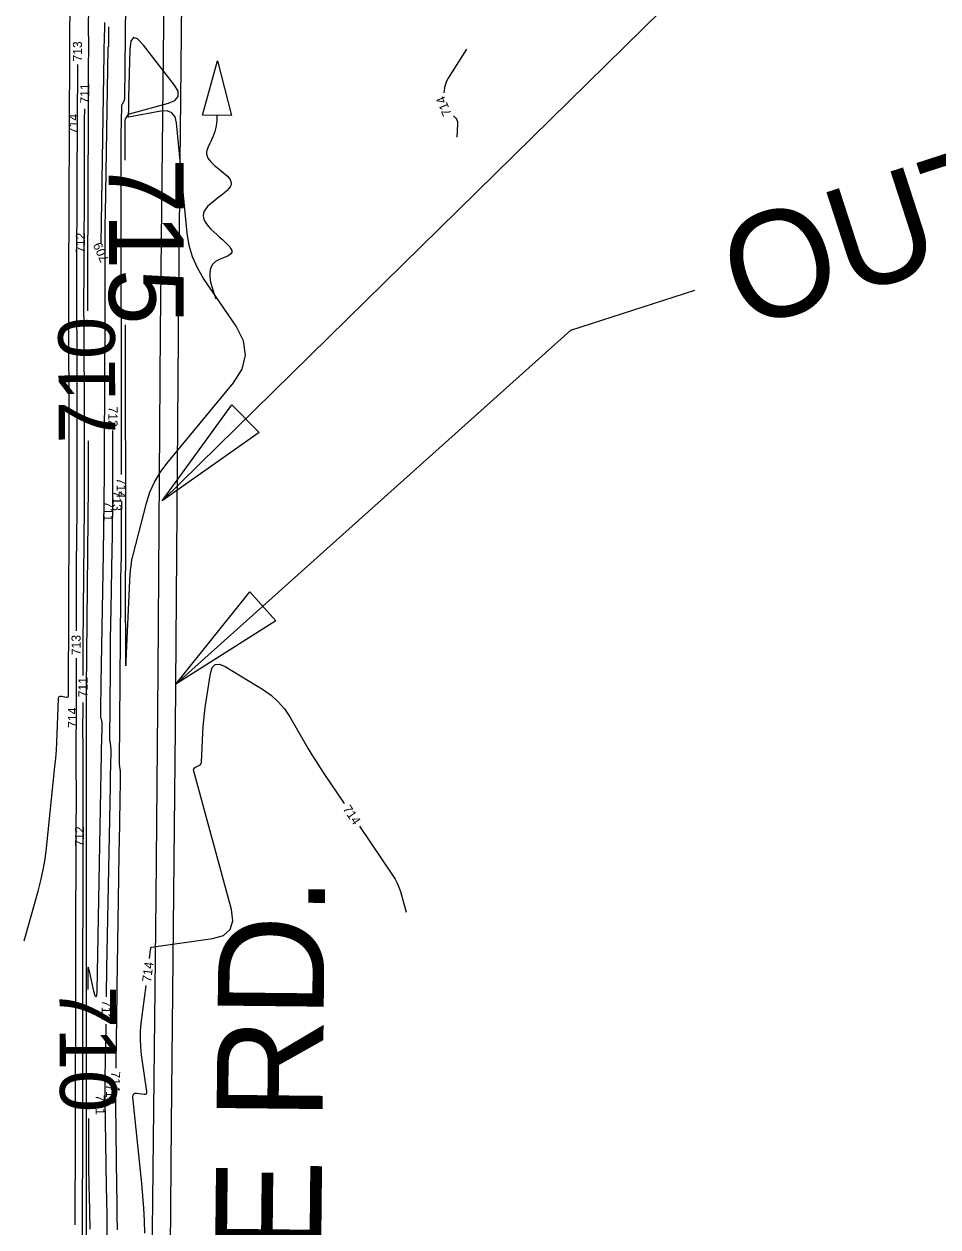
# Model space of a CAD drawing. Extents: x -468548933 to 3387700, y -306089263 to 1207014.
# Drawn here: x 1835208 to 1835612, y 537245 to 537776 of the extents above; entities that cross this region are included whole.
import ezdxf

# ---------------------------------------------------------------- set-up
doc = ezdxf.new("R2010")
doc.units = 0
for name, color, linetype in [('DT_X_Contour_Minor', 7, 'Continuous'), ('Level 19', 7, 'Continuous'), ('Level 40', 7, 'Continuous'), ('Level 56', 7, 'Continuous')]:
    doc.layers.add(name, color=color, linetype=linetype)

msp = doc.modelspace()

# ---------------------------------------------------------------- linework, layer by layer
at = {"layer": 'DT_X_Contour_Minor'}
for points in [[(1835208.43, 537371.04), (1835214.63, 537392.88), (1835215.86, 537397.58), (1835216.88, 537402.32), (1835217.69, 537407.1), (1835218.3, 537411.92), (1835222.08, 537447.93), (1835222.43, 537451.53), (1835222.71, 537455.13), (1835222.93, 537458.74), (1835223.09, 537462.36), (1835223.63, 537477.88), (1835223.73, 537478.46), (1835223.99, 537478.83), (1835224.41, 537479), (1835224.99, 537478.98), (1835227.14, 537478.57), (1835227.55, 537478.56), (1835227.84, 537478.68), (1835228.01, 537478.94), (1835228.07, 537479.34), (1835228.35, 537556.11), (1835228.35, 537556.14), (1835228.35, 537556.17), (1835228.35, 537556.2), (1835228.35, 537556.23), (1835228.35, 537556.33), (1835228.35, 537556.35), (1835228.35, 537556.37), (1835228.35, 537556.39), (1835228.35, 537556.42), (1835228.33, 537573.32), (1835228.33, 537576.94), (1835228.32, 537580.57), (1835228.32, 537584.19), (1835228.32, 537587.81), (1835228.25, 537656.96), (1835228.25, 537657.19), (1835228.25, 537657.43), (1835228.25, 537657.67), (1835228.25, 537657.9), (1835228.24, 537658.68), (1835228.24, 537658.84), (1835228.24, 537659.01), (1835228.24, 537659.18), (1835228.24, 537659.34), (1835228.25, 537660.88), (1835228.25, 537661.21), (1835228.25, 537661.54), (1835228.25, 537661.87), (1835228.25, 537662.2), (1835228.69, 537763.25), (1835228.69, 537763.33), (1835228.68, 537763.41), (1835228.68, 537763.49), (1835228.66, 537763.57), (1835228.61, 537763.84), (1835228.6, 537763.89), (1835228.6, 537763.95), (1835228.59, 537764), (1835228.59, 537764.06), (1835229.14, 537840.75)], [(1835253.59, 537826.49), (1835252.72, 537742.53), (1835252.69, 537742.17), (1835252.62, 537741.83), (1835252.49, 537741.51), (1835252.32, 537741.2), (1835251.69, 537740.2), (1835251.57, 537739.98), (1835251.49, 537739.75), (1835251.43, 537739.52), (1835251.41, 537739.27), (1835251.2, 537726.2), (1835251.17, 537723.4), (1835251.14, 537720.6), (1835251.12, 537717.79), (1835251.12, 537714.99), (1835251.35, 537576.81)], [(1835236.55, 537648.98), (1835236.55, 537655.87), (1835236.57, 537664.54), (1835236.83, 537735.51), (1835236.85, 537739.51), (1835236.86, 537743.51), (1835236.88, 537747.51), (1835236.89, 537751.51), (1835236.97, 537770.14), (1835236.97, 537770.17), (1835236.97, 537770.19), (1835236.97, 537770.21), (1835236.97, 537770.23), (1835236.95, 537770.3), (1835236.95, 537770.31), (1835236.95, 537770.33), (1835236.95, 537770.34), (1835236.95, 537770.36), (1835237.07, 537786.75)], [(1835245.75, 537774.39), (1835245.66, 537765.88), (1835245.66, 537765.8), (1835245.64, 537765.72), (1835245.61, 537765.64), (1835245.57, 537765.56), (1835245.42, 537765.32), (1835245.39, 537765.27), (1835245.37, 537765.21), (1835245.35, 537765.16), (1835245.35, 537765.1), (1835244.17, 537691.78), (1835244.11, 537687.07), (1835244.06, 537682.36), (1835244.04, 537677.65), (1835244.04, 537672.95), (1835244.06, 537657.57), (1835244.07, 537654.27), (1835244.07, 537650.97), (1835244.06, 537647.68), (1835244.05, 537644.38), (1835243.86, 537589.16), (1835243.79, 537577.33), (1835243.69, 537565.5), (1835243.54, 537553.67), (1835243.35, 537541.84), (1835242.32, 537484.75), (1835242.29, 537483.02), (1835242.27, 537481.29), (1835242.25, 537479.56), (1835242.23, 537477.83), (1835242.17, 537470.34), (1835242.18, 537470.05), (1835242.21, 537469.76), (1835242.25, 537469.47), (1835242.32, 537469.19), (1835242.62, 537468.07), (1835242.64, 537467.97), (1835242.66, 537467.87), (1835242.68, 537467.77), (1835242.7, 537467.66), (1835242.74, 537467.33), (1835242.75, 537467.26), (1835242.76, 537467.18), (1835242.76, 537467.11), (1835242.76, 537467.04), (1835242.72, 537464.1), (1835242.71, 537463.47), (1835242.7, 537462.84), (1835242.68, 537462.21), (1835242.67, 537461.58), (1835240.52, 537348.87), (1835240.4, 537346.79), (1835240.15, 537346.07), (1835239.76, 537346.72), (1835239.24, 537348.74), (1835237.31, 537357.56), (1835236.95, 537358.97), (1835236.7, 537359.43), (1835236.55, 537358.93), (1835236.51, 537357.47), (1835236.55, 537349.55)], [(1835243.95, 537776.29), (1835243.9, 537771.72), (1835243.9, 537771.71), (1835243.9, 537771.69), (1835243.89, 537771.67), (1835243.88, 537771.65), (1835243.85, 537771.6), (1835243.84, 537771.59), (1835243.84, 537771.58), (1835243.83, 537771.57), (1835243.83, 537771.55), (1835242.34, 537678.75)], [(1835253.17, 537538.02), (1835253.11, 537530.73), (1835253.1, 537529.11), (1835253.1, 537527.49), (1835253.09, 537525.88), (1835253.09, 537524.26), (1835253.16, 537498.02), (1835253.21, 537493.8), (1835253.31, 537492.4), (1835253.48, 537493.8), (1835253.71, 537498.01), (1835255.33, 537533.05), (1835255.38, 537533.88), (1835255.45, 537534.71), (1835255.54, 537535.54), (1835255.65, 537536.37), (1835256.07, 537539.07), (1835256.16, 537539.65), (1835256.27, 537540.22), (1835256.4, 537540.79), (1835256.53, 537541.36), (1835262.44, 537564.17), (1835263.95, 537568.93), (1835265.95, 537573.44), (1835268.44, 537577.7), (1835271.42, 537581.71), (1835300.9, 537617.25), (1835304.72, 537623.32), (1835306.18, 537629.5), (1835305.31, 537635.79), (1835302.08, 537642.2), (1835287.71, 537663.3), (1835284.95, 537667.93), (1835282.83, 537672.8), (1835281.34, 537677.9), (1835280.5, 537683.23), (1835275.76, 537731.97), (1835275.1, 537734.67), (1835273.73, 537736.44), (1835271.65, 537737.26), (1835268.87, 537737.14), (1835254.59, 537734.47), (1835254.45, 537734.46), (1835254.36, 537734.51), (1835254.32, 537734.6), (1835254.34, 537734.74), (1835254.51, 537735.36), (1835254.53, 537735.43), (1835254.56, 537735.5), (1835254.59, 537735.57), (1835254.63, 537735.64), (1835254.75, 537735.87), (1835254.79, 537735.91), (1835254.82, 537735.95), (1835254.87, 537735.97), (1835254.92, 537735.99), (1835272.12, 537740.64), (1835275.05, 537741.89), (1835276.48, 537743.65), (1835276.4, 537745.91), (1835274.82, 537748.67), (1835261.15, 537766.33), (1835258.57, 537769.04), (1835256.7, 537769.61), (1835255.53, 537768.04), (1835255.06, 537764.33), (1835254.57, 537743.34), (1835254.55, 537742.48), (1835254.54, 537741.61), (1835254.52, 537740.74), (1835254.51, 537739.87), (1835254.48, 537736.69), (1835254.45, 537736.27), (1835254.36, 537735.86), (1835254.21, 537735.47), (1835254.01, 537735.1), (1835253.26, 537733.92), (1835253.12, 537733.66), (1835253.02, 537733.39), (1835252.95, 537733.11), (1835252.93, 537732.81), (1835252.9, 537730.95), (1835252.89, 537730.55), (1835252.89, 537730.15), (1835252.89, 537729.76), (1835252.89, 537729.36), (1835252.91, 537715.56)], [(1835403.76, 537764.52), (1835395.67, 537751.74), (1835394.94, 537750.43), (1835394.39, 537749.06), (1835394.01, 537747.64), (1835393.8, 537746.16), (1835393.73, 537745.23)], [(1835231.97, 537757.72), (1835231.75, 537706.34), (1835231.72, 537700.33), (1835231.7, 537694.33), (1835231.67, 537688.32), (1835231.65, 537682.31), (1835231.58, 537661.8), (1835231.57, 537658.04), (1835231.57, 537654.29), (1835231.57, 537650.53), (1835231.59, 537646.77), (1835231.66, 537634.51), (1835231.67, 537631.88), (1835231.68, 537629.25), (1835231.69, 537626.62), (1835231.7, 537623.99), (1835231.74, 537574.7), (1835231.74, 537569.08), (1835231.72, 537563.45), (1835231.69, 537557.82), (1835231.65, 537552.2), (1835231.48, 537533.82), (1835231.45, 537529.88), (1835231.43, 537525.94), (1835231.41, 537522), (1835231.4, 537518.06), (1835231.39, 537507.73)], [(1835234.46, 537488.13), (1835234.46, 537489.58), (1835234.47, 537492.6), (1835234.48, 537495.63), (1835234.5, 537498.66), (1835234.52, 537501.68), (1835235.08, 537562.59), (1835235.11, 537567.03), (1835235.14, 537571.47), (1835235.15, 537575.91), (1835235.15, 537580.35), (1835235.14, 537594.85), (1835235.13, 537597.96), (1835235.12, 537601.06), (1835235.11, 537604.17), (1835235.1, 537607.28), (1835234.93, 537636.88), (1835234.9, 537643.22), (1835234.88, 537649.56), (1835234.88, 537655.9), (1835234.9, 537662.25), (1835235.09, 537714.6), (1835235.12, 537720.86), (1835235.14, 537727.12), (1835235.17, 537733.37), (1835235.19, 537738.12)], [(1835397.92, 537735.09), (1835398.34, 537734.73), (1835398.99, 537734.04), (1835399.44, 537733.27), (1835399.69, 537732.41), (1835399.74, 537731.47), (1835399.45, 537725.71)], [(1835253.03, 537642.9), (1835253.2, 537540.77), (1835253.2, 537540.61), (1835253.2, 537540.44), (1835253.2, 537540.28), (1835253.2, 537540.11), (1835253.2, 537539.58), (1835253.2, 537539.46), (1835253.19, 537539.35), (1835253.19, 537539.23), (1835253.19, 537539.12), (1835253.18, 537538.53), (1835253.18, 537538.4), (1835253.18, 537538.27), (1835253.17, 537538.14), (1835253.17, 537538.02)], [(1835236.07, 537220.78), (1835235.98, 537252.2), (1835235.98, 537252.49), (1835235.98, 537252.78), (1835235.98, 537253.07), (1835235.98, 537253.35), (1835235.98, 537254.29), (1835235.98, 537254.49), (1835235.98, 537254.69), (1835235.98, 537254.89), (1835235.98, 537255.09), (1835235.98, 537256.04), (1835235.98, 537256.24), (1835235.98, 537256.44), (1835235.98, 537256.64), (1835235.98, 537256.85), (1835236.05, 537366.66), (1835236.05, 537366.77), (1835236.05, 537366.87), (1835236.05, 537366.98), (1835236.05, 537367.08), (1835236.05, 537367.43), (1835236.05, 537367.5), (1835236.05, 537367.58), (1835236.05, 537367.65), (1835236.05, 537367.72), (1835235.99, 537468.53), (1835235.99, 537469.91), (1835235.99, 537471.29), (1835235.99, 537472.66), (1835235.99, 537474.04), (1835235.99, 537478.55), (1835236, 537479.51), (1835236, 537480.48), (1835236.01, 537481.44), (1835236.01, 537482.41), (1835236.83, 537572.04), (1835236.85, 537573.76), (1835236.85, 537575.48), (1835236.86, 537577.21), (1835236.86, 537578.93), (1835236.85, 537584.56), (1835236.85, 537585.77), (1835236.85, 537586.97), (1835236.84, 537588.18), (1835236.84, 537589.39), (1835236.82, 537591.72)], [(1835244.8, 537346.22), (1835244.81, 537347.16), (1835244.87, 537351.03), (1835244.94, 537354.9), (1835245.01, 537358.76), (1835246.55, 537439.29), (1835246.58, 537441.26), (1835246.62, 537443.24), (1835246.65, 537445.21), (1835246.68, 537447.19), (1835246.81, 537455.78), (1835246.8, 537456.09), (1835246.79, 537456.4), (1835246.77, 537456.72), (1835246.73, 537457.03), (1835246.58, 537458.15), (1835246.56, 537458.31), (1835246.53, 537458.48), (1835246.5, 537458.64), (1835246.46, 537458.79), (1835246.32, 537459.31), (1835246.29, 537459.42), (1835246.27, 537459.54), (1835246.26, 537459.65), (1835246.26, 537459.76), (1835246.52, 537490.79), (1835246.58, 537497.44), (1835246.66, 537504.08), (1835246.75, 537510.73), (1835246.87, 537517.38), (1835247.34, 537543.74), (1835247.43, 537549.39), (1835247.5, 537555.04), (1835247.55, 537560.69), (1835247.58, 537566.34), (1835247.68, 537594.63), (1835247.69, 537596.14)], [(1835251.37, 537564.81), (1835251.37, 537562.55), (1835251.36, 537559.85), (1835251.35, 537557.16), (1835251.32, 537548.35), (1835251.31, 537546.47), (1835251.3, 537544.58), (1835251.27, 537542.69), (1835251.24, 537540.81), (1835251.07, 537531.06), (1835251.03, 537528.97), (1835251, 537526.88), (1835250.98, 537524.79), (1835250.96, 537522.7), (1835250.35, 537449.38), (1835250.35, 537449.35), (1835250.36, 537449.31), (1835250.36, 537449.28), (1835250.37, 537449.24), (1835250.4, 537449.13), (1835250.4, 537449.11), (1835250.41, 537449.09), (1835250.41, 537449.06), (1835250.42, 537449.04), (1835250.73, 537446.65), (1835250.79, 537446.14), (1835250.83, 537445.62), (1835250.85, 537445.11), (1835250.85, 537444.59), (1835250.64, 537429.77), (1835250.59, 537426.71), (1835250.54, 537423.64), (1835250.49, 537420.58), (1835250.43, 537417.51), (1835250.24, 537407.5), (1835250.2, 537405.35), (1835250.16, 537403.2), (1835250.13, 537401.06), (1835250.1, 537398.91), (1835249.41, 537350.54), (1835249.34, 537345.31), (1835249.26, 537340.08), (1835249.19, 537334.85), (1835249.11, 537329.62), (1835248.9, 537314.87)], [(1835231.38, 537495.73), (1835231.36, 537466.67), (1835231.35, 537462.26), (1835231.35, 537457.86), (1835231.35, 537453.46), (1835231.35, 537449.06), (1835231.36, 537434.67), (1835231.36, 537431.59), (1835231.36, 537428.51), (1835231.35, 537425.43), (1835231.34, 537422.34), (1835231.13, 537364.42), (1835231.11, 537359.75), (1835231.1, 537355.09), (1835231.09, 537350.42), (1835231.09, 537345.76), (1835231.08, 537330.52), (1835231.08, 537327.25), (1835231.07, 537323.98), (1835231.06, 537320.72), (1835231.06, 537317.45), (1835230.92, 537270.17), (1835230.9, 537260.03), (1835230.89, 537249.9), (1835230.89, 537245.73)], [(1835263.81, 537363.23), (1835264.29, 537367.07), (1835264.31, 537367.21), (1835264.33, 537367.34), (1835264.34, 537367.47), (1835264.36, 537367.6), (1835264.41, 537368.04), (1835264.44, 537368.12), (1835264.48, 537368.18), (1835264.54, 537368.23), (1835264.62, 537368.25), (1835291.55, 537371.99), (1835296.41, 537373.39), (1835299.44, 537376), (1835300.65, 537379.81), (1835300.03, 537384.83), (1835283.35, 537445.93), (1835283.28, 537446.48), (1835283.38, 537446.95), (1835283.66, 537447.34), (1835284.13, 537447.65), (1835285.93, 537448.52), (1835286.26, 537448.74), (1835286.51, 537449.02), (1835286.67, 537449.36), (1835286.74, 537449.76), (1835287.34, 537462.85), (1835287.51, 537465.65), (1835287.74, 537468.44), (1835288.06, 537471.23), (1835288.44, 537474.01), (1835290.73, 537489.03), (1835291.5, 537491.64), (1835292.85, 537493.01), (1835294.77, 537493.15), (1835297.26, 537492.07), (1835314.16, 537481.7), (1835317.6, 537479.29), (1835320.67, 537476.53), (1835323.36, 537473.4), (1835325.68, 537469.91), (1835333.75, 537456.04), (1835335.51, 537453.09), (1835337.31, 537450.16), (1835339.16, 537447.27), (1835341.07, 537444.4), (1835349.75, 537431.57)], [(1835234.33, 537233.31), (1835234.29, 537247.16), (1835234.28, 537250.13), (1835234.28, 537253.09), (1835234.28, 537256.06), (1835234.29, 537259.03), (1835234.33, 537272.98), (1835234.34, 537275.97), (1835234.34, 537278.96), (1835234.35, 537281.95), (1835234.35, 537284.93), (1835234.39, 537355.46), (1835234.39, 537359.2), (1835234.4, 537362.95), (1835234.41, 537366.69), (1835234.42, 537370.43), (1835234.47, 537382.65), (1835234.48, 537385.27), (1835234.48, 537387.89), (1835234.48, 537390.51), (1835234.48, 537393.13), (1835234.45, 537458.17), (1835234.44, 537462.49), (1835234.44, 537466.81), (1835234.45, 537471.13), (1835234.45, 537475.46), (1835234.45, 537476.13)], [(1835356.48, 537421.63), (1835371.12, 537399.98), (1835372.19, 537398.27), (1835373.11, 537396.48), (1835373.89, 537394.63), (1835374.53, 537392.71), (1835377.16, 537383.59)], [(1835261.78, 537241.97), (1835261.6, 537247.47), (1835261.32, 537252.97), (1835260.92, 537258.46), (1835260.42, 537263.94), (1835256.51, 537302.05), (1835256.55, 537302.9), (1835256.85, 537303.47), (1835257.43, 537303.76), (1835258.28, 537303.77), (1835261.5, 537303.34), (1835262.1, 537303.35), (1835262.49, 537303.55), (1835262.69, 537303.95), (1835262.68, 537304.54), (1835260.31, 537320.69), (1835259.92, 537324.15), (1835259.77, 537327.61), (1835259.85, 537331.08), (1835260.17, 537334.55), (1835262.3, 537351.33)], [(1835245.53, 537208.54), (1835245.2, 537237.69), (1835245.13, 537243.93), (1835245.05, 537250.18), (1835244.96, 537256.42), (1835244.87, 537262.67), (1835244.29, 537300.93), (1835244.27, 537303.35), (1835244.26, 537305.76), (1835244.26, 537308.18), (1835244.29, 537310.6), (1835244.4, 537318.49), (1835244.43, 537320.18), (1835244.45, 537321.87), (1835244.47, 537323.56), (1835244.5, 537325.26), (1835244.63, 537334.22)], [(1835248.8, 537302.87), (1835248.83, 537300.95), (1835248.84, 537300.38), (1835248.85, 537299.81), (1835248.85, 537299.25), (1835248.86, 537298.68), (1835249.28, 537262.45), (1835249.35, 537256.13), (1835249.44, 537249.82), (1835249.54, 537243.5)], [(1835236.83, 537292.61), (1835236.93, 537271.84), (1835236.95, 537268.57), (1835236.99, 537265.31), (1835237.04, 537262.04), (1835237.1, 537258.77), (1835237.41, 537243.69)]]:
    msp.add_lwpolyline(points, dxfattribs=at)
at = {"layer": 'Level 40'}
for p, q in [((1835449.84, 537640.44), (1835504.55, 537658.2)), ((1835449.84, 537640.44), (1835275.42, 537484.22)), ((1835269.4, 537565.22), (1835300.08, 537607.55)), ((1835300.08, 537607.55), (1835312.14, 537595.33)), ((1835312.14, 537595.33), (1835269.4, 537565.22)), ((1835275.42, 537484.22), (1835308.12, 537525.01)), ((1835308.12, 537525.01), (1835319.58, 537512.22)), ((1835319.58, 537512.22), (1835275.42, 537484.22))]:
    msp.add_line(p, q, dxfattribs=at)
msp.add_lwpolyline([(1835269.4, 537565.22), (1835546.87, 537837.73), (1835603.69, 537856.17)], dxfattribs=at)
at = {"layer": 'Level 56'}
for p, q in [((1835287.16, 537735.35), (1835293.78, 537759.3)), ((1835293.78, 537759.3), (1835300.03, 537735.25)), ((1835300.03, 537735.25), (1835287.16, 537735.35))]:
    msp.add_line(p, q, dxfattribs=at)
for points in [[(1835272.54, 537989.9), (1835270.63, 537829.71), (1835268.58, 537639.91), (1835267.46, 537489.92), (1835266.63, 537389.92), (1835264.41, 537189.93), (1835263.9, 537104.93), (1835263.77, 536939.93), (1835262.99, 536824.67)], [(1835271.56, 536827.69), (1835271.95, 537089.9), (1835273.57, 537289.9), (1835275.29, 537464.69), (1835276.71, 537656.89), (1835279.46, 537914.68), (1835280.54, 537989.88)]]:
    msp.add_lwpolyline(points, dxfattribs=at)
msp.add_spline([(1835293.53, 537735.33), (1835293.53, 537734.38), (1835291.21, 537724.52), (1835288.99, 537718.28), (1835299.92, 537705.48), (1835287.44, 537691.02), (1835299.7, 537674.13), (1835292.97, 537670.78), (1835293.03, 537654.3)], degree=3, dxfattribs=at)

# ---------------------------------------------------------------- texts
at = {"layer": 'Level 19'}
for s, height, rotation, p in [('713', 4, 90.0521, (1835234, 537759.05)), ('711', 4, 89.7523, (1835237.2, 537740.46)), ('714', 4, 112.4452, (1835397.24, 537735.91)), ('714', 4, 89.7516, (1835232.19, 537726.98)), ('715', 33, 270.0941, (1835245.81, 537716.53)), ('712', 4, 89.7905, (1835235.28, 537674.57)), ('709', 4, 113.8187, (1835245.99, 537671.53)), ('710', 25, 90.308, (1835248.79, 537590.65)), ('712', 4, 269.8901, (1835245.71, 537606.79)), ('714', 4, 270.0819, (1835249.35, 537575.28)), ('711', 4, 269.4037, (1835243.65, 537565.03)), ('713', 4, 269.799, (1835247.5, 537569.66)), ('713', 4, 89.9476, (1835233.38, 537497.05)), ('711', 4, 89.9476, (1835236.45, 537478.47)), ('714', 4, 89.9476, (1835231.81, 537464.99)), ('714', 4, 304.0829, (1835348.95, 537429.18)), ('712', 4, 89.9897, (1835234.92, 537412.58)), ('714', 4, 82.7838, (1835264.47, 537352.59)), ('710', 25, 270.2836, (1835224.04, 537351.1)), ('712', 4, 269.1796, (1835242.78, 537344.89)), ('714', 4, 269.5137, (1835246.86, 537313.36)), ('713', 4, 270.315, (1835244.53, 537307.71)), ('711', 4, 270.842, (1835239.99, 537303.07))]:
    msp.add_text(s, height=height, rotation=rotation, dxfattribs=at).set_placement(p)
at = {"layer": 'Level 40'}
for s, rotation, p in [("OUTFALL 'M'", 17.9864, (1835526.17, 537640.31)), ('WHETSTONE RD.', 89.3978, (1835335.8, 536874.43))]:
    msp.add_text(s, height=46.8, rotation=rotation, dxfattribs=at).set_placement(p)

doc.saveas('drawing.dxf')
